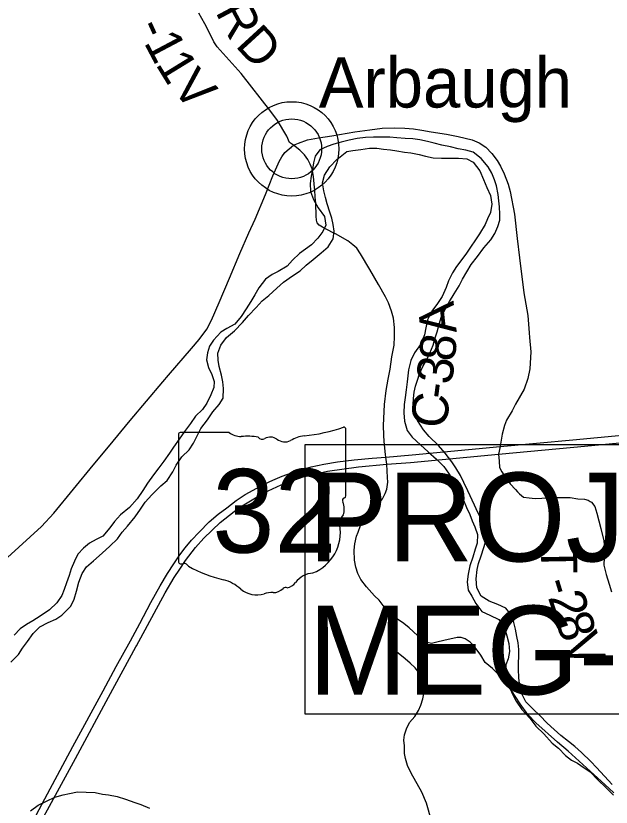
# Model space of a CAD drawing. Extents: x -13.7 to 34, y 0 to 32.3.
# Drawn here: x 23.927 to 24.865, y 17.887 to 19.134 of the extents above; entities that cross this region are included whole.
import ezdxf

# ---------------------------------------------------------------- set-up
doc = ezdxf.new("R2010")
doc.units = 0
for name, color, linetype in [('GM_X_County_Road', 7, 'Continuous'), ('GM_X_County_Road_Text', 7, 'Continuous'), ('GM_X_Major_River', 7, 'Continuous'), ('GM_X_Minor_River', 7, 'Continuous'), ('GM_X_State_Location', 7, 'Continuous'), ('GM_X_State_Route', 7, 'Continuous'), ('GM_X_State_Shield', 7, 'Continuous'), ('GM_X_Township_Road', 7, 'Continuous'), ('GM_X_Township_Road_Text', 7, 'Continuous'), ('GM_X_Unincorporated', 7, 'Continuous'), ('GM_X_Unincorporated_Location', 7, 'Continuous'), ('GM_X_Unincorporated_Text', 7, 'Continuous'), ('SH_Masking', 7, 'Continuous'), ('SH_Text', 7, 'Continuous')]:
    doc.layers.add(name, color=color, linetype=linetype)

msp = doc.modelspace()

# ---------------------------------------------------------------- linework, layer by layer
at = {"layer": 'GM_X_County_Road'}
for points in [[(23.8899, 18.259), (23.9313, 18.2966), (23.9669, 18.3292), (23.9865, 18.3504), (24.0483, 18.4258), (24.0727, 18.455), (24.1068, 18.4962), (24.1584, 18.5574), (24.1675, 18.568), (24.2035, 18.61), (24.2158, 18.6242), (24.2276, 18.6402), (24.235, 18.6547), (24.2473, 18.6825), (24.2635, 18.7206), (24.2801, 18.7596), (24.2943, 18.7922), (24.3038, 18.8138), (24.3201, 18.8525), (24.332, 18.882), (24.3401, 18.9009), (24.3421, 18.9046), (24.346, 18.9118), (24.3508, 18.9189), (24.3576, 18.9245), (24.3643, 18.9302), (24.3725, 18.9336), (24.3868, 18.939), (24.4038, 18.9419), (24.4249, 18.9452), (24.4614, 18.9515), (24.4849, 18.9545), (24.5045, 18.9572), (24.5239, 18.9579), (24.54, 18.9572), (24.554, 18.956), (24.5669, 18.9541), (24.5818, 18.9517), (24.6057, 18.9476), (24.6243, 18.9442), (24.6464, 18.939), (24.6575, 18.9343), (24.6679, 18.9274), (24.6771, 18.9173), (24.6857, 18.9065), (24.6909, 18.8971), (24.6968, 18.8855), (24.7031, 18.8691), (24.7064, 18.8574), (24.7132, 18.8215), (24.7174, 18.7834), (24.7211, 18.7529), (24.7279, 18.6974), (24.7338, 18.6617), (24.7363, 18.6345)], [(24.3979, 18.8598), (24.3976, 18.8639), (24.3961, 18.881), (24.3939, 18.893), (24.3909, 18.9007), (24.3872, 18.908), (24.3821, 18.915), (24.3744, 18.9227), (24.3643, 18.9302)], [(24.427, 18.7924), (24.4103, 18.8011), (24.4051, 18.8041), (24.4018, 18.8079), (24.4006, 18.8122), (24.4005, 18.8186), (24.3999, 18.8388), (24.3987, 18.8485), (24.3979, 18.8598)], [(24.5117, 18.4275), (24.5101, 18.4386), (24.5096, 18.4425), (24.5077, 18.4633), (24.5071, 18.4731), (24.5062, 18.4882), (24.508, 18.5217), (24.5108, 18.5437), (24.5138, 18.5615), (24.5167, 18.5772), (24.5194, 18.5966), (24.5231, 18.615), (24.5239, 18.6289), (24.5237, 18.6431), (24.522, 18.6576), (24.5193, 18.6688), (24.5142, 18.6819), (24.5096, 18.6911), (24.4987, 18.7109), (24.4847, 18.7344), (24.4701, 18.7593), (24.4645, 18.7681), (24.4581, 18.7735), (24.4502, 18.7798), (24.4305, 18.7906), (24.427, 18.7924)], [(24.7363, 18.6345), (24.7369, 18.6274), (24.7387, 18.6045), (24.7372, 18.5776), (24.7339, 18.5624), (24.7285, 18.5455), (24.7146, 18.5219), (24.7091, 18.5116), (24.7005, 18.4966), (24.6971, 18.4883), (24.6935, 18.4749), (24.6911, 18.4592), (24.6903, 18.4555), (24.6879, 18.4434)], [(24.4794, 18.234), (24.4709, 18.2456), (24.4661, 18.2551), (24.4627, 18.2652), (24.4606, 18.2759), (24.4602, 18.2919), (24.461, 18.3018), (24.4636, 18.3141), (24.4665, 18.3204), (24.4701, 18.3305), (24.4779, 18.3412), (24.4863, 18.3503), (24.4958, 18.3619), (24.5046, 18.3728), (24.5091, 18.3812), (24.5118, 18.3882), (24.5131, 18.3989), (24.5126, 18.4063), (24.5117, 18.4275)], [(24.5166, 18.1887), (24.5137, 18.1928), (24.511, 18.1974), (24.5074, 18.2024), (24.4996, 18.213), (24.492, 18.2199), (24.4794, 18.234)], [(24.5823, 17.8652), (24.5742, 17.8927), (24.5669, 17.9101), (24.5498, 17.9401), (24.5445, 17.9522), (24.541, 17.9633), (24.5396, 17.9709), (24.5394, 17.9833), (24.5387, 17.9921), (24.5397, 18.0004), (24.5428, 18.0101), (24.5475, 18.02), (24.5556, 18.0295), (24.5616, 18.0389), (24.5655, 18.0473), (24.5686, 18.0574), (24.5703, 18.0678), (24.5701, 18.0751), (24.5687, 18.0839), (24.5672, 18.089), (24.5625, 18.0981), (24.5564, 18.1062), (24.5486, 18.1134), (24.5404, 18.1207), (24.5321, 18.1274), (24.5248, 18.133), (24.5185, 18.1388), (24.5164, 18.1417), (24.5153, 18.1463), (24.5144, 18.1512), (24.5143, 18.1573), (24.5149, 18.1645), (24.515, 18.1698), (24.516, 18.1767), (24.5166, 18.1887)]]:
    msp.add_lwpolyline(points, dxfattribs=at)
at = {"layer": 'GM_X_Major_River'}
for points in [[(24.6866, 18.802), (24.6897, 18.8123), (24.6897, 18.8217), (24.6893, 18.8331), (24.6885, 18.8426), (24.6874, 18.8529), (24.6848, 18.8665), (24.6817, 18.876), (24.6772, 18.8863), (24.6715, 18.8965), (24.6605, 18.9094), (24.6476, 18.9193), (24.6362, 18.9223), (24.6241, 18.9246), (24.6119, 18.9277), (24.5986, 18.9307), (24.5861, 18.9338), (24.5759, 18.936), (24.5637, 18.9387), (24.5527, 18.9402), (24.5406, 18.941), (24.5273, 18.9422), (24.5163, 18.9429), (24.4908, 18.9429), (24.4783, 18.9426), (24.465, 18.9407), (24.4525, 18.9384), (24.4399, 18.9354), (24.4281, 18.932), (24.4175, 18.9286), (24.4061, 18.9233), (24.3985, 18.913), (24.3962, 18.9024), (24.3947, 18.8925), (24.3924, 18.8815), (24.3909, 18.8698), (24.3912, 18.8576), (24.3958, 18.8447), (24.4034, 18.8318), (24.4132, 18.8182), (24.4155, 18.8045), (24.4109, 18.7943), (24.4029, 18.784), (24.3931, 18.7734), (24.3836, 18.7662), (24.3741, 18.7598), (24.363, 18.7491), (24.3547, 18.7397), (24.3402, 18.7313), (24.3307, 18.7264), (24.3205, 18.7192), (24.3098, 18.7055), (24.3034, 18.6942), (24.2973, 18.6839), (24.29, 18.6722), (24.2821, 18.6604), (24.2718, 18.6483), (24.2593, 18.6411), (24.2498, 18.6354), (24.2384, 18.6229), (24.2319, 18.6134), (24.2288, 18.6031), (24.2273, 18.5918), (24.2303, 18.5796), (24.2356, 18.5686), (24.2394, 18.558), (24.239, 18.5485), (24.2341, 18.5367), (24.2276, 18.5238), (24.2208, 18.5136), (24.2101, 18.503), (24.2018, 18.4916), (24.1926, 18.4787), (24.1843, 18.4666), (24.1755, 18.4541), (24.1691, 18.4446), (24.1599, 18.4321), (24.1523, 18.4214), (24.1436, 18.4108), (24.1341, 18.3972), (24.1268, 18.3858), (24.1181, 18.3725), (24.1059, 18.3592), (24.0919, 18.3475), (24.082, 18.3372), (24.0751, 18.327), (24.0637, 18.3141), (24.0531, 18.3088), (24.0428, 18.3027), (24.0333, 18.2952), (24.0246, 18.2857), (24.0193, 18.2747), (24.0139, 18.2625), (24.0109, 18.2519), (24.0067, 18.2402), (24.0029, 18.2299), (23.9991, 18.2204), (23.9915, 18.2087), (23.9797, 18.1977), (23.9649, 18.1878), (23.9535, 18.1806)], [(23.9185, 18.115), (23.931, 18.1275), (23.9371, 18.137), (23.9451, 18.148), (23.9538, 18.1605), (23.9645, 18.1707), (23.9778, 18.1776), (23.9899, 18.1829), (23.9994, 18.1893), (24.0131, 18.2033), (24.0185, 18.2143), (24.0223, 18.2272), (24.0261, 18.2413), (24.0314, 18.2549), (24.0383, 18.2656), (24.0493, 18.275), (24.063, 18.2872), (24.0747, 18.2982), (24.0869, 18.3099), (24.0945, 18.3202), (24.1029, 18.3296), (24.115, 18.3444), (24.123, 18.3562), (24.1306, 18.3676), (24.1409, 18.3789), (24.1553, 18.3934), (24.1652, 18.4017), (24.174, 18.4153), (24.1793, 18.4256), (24.1884, 18.4389), (24.2002, 18.4502), (24.207, 18.4605), (24.2124, 18.4722), (24.2185, 18.4836), (24.2287, 18.4973), (24.2375, 18.5098), (24.2474, 18.5215), (24.2534, 18.5314), (24.2542, 18.5466), (24.2531, 18.5572), (24.2508, 18.5675), (24.2474, 18.5815), (24.2455, 18.5914), (24.2452, 18.6024), (24.2497, 18.6149), (24.2589, 18.627), (24.2714, 18.6376), (24.2843, 18.6509), (24.2935, 18.6619), (24.3056, 18.6744), (24.3151, 18.685), (24.3254, 18.6934), (24.3383, 18.7051), (24.3489, 18.7142), (24.363, 18.7245), (24.3748, 18.7324), (24.3847, 18.7412), (24.3957, 18.7499), (24.4082, 18.7605), (24.4192, 18.77), (24.4272, 18.7825), (24.4284, 18.795), (24.4269, 18.8056), (24.425, 18.8151), (24.422, 18.8246), (24.4174, 18.8379), (24.4148, 18.8478), (24.4121, 18.8584), (24.4102, 18.8709), (24.4133, 18.8834), (24.422, 18.8963), (24.4327, 18.9081), (24.4486, 18.9202), (24.4581, 18.9221), (24.4707, 18.9236), (24.4843, 18.9255), (24.4961, 18.9259), (24.5064, 18.9243), (24.5174, 18.9232), (24.5272, 18.9217), (24.5394, 18.9194), (24.5493, 18.9182), (24.5629, 18.9159), (24.5728, 18.9133), (24.585, 18.9106), (24.5979, 18.9098), (24.6248, 18.9098), (24.6381, 18.9087), (24.6476, 18.9037), (24.6582, 18.8901), (24.6643, 18.8764), (24.6696, 18.8635), (24.6753, 18.851), (24.6775, 18.8373), (24.6752, 18.8244), (24.6707, 18.8145), (24.6665, 18.8051), (24.6577, 18.7907)], [(24.8668, 17.9222), (24.8551, 17.9355), (24.8426, 17.9492), (24.8335, 17.9587), (24.8187, 17.9727), (24.808, 17.9822), (24.7982, 17.9902), (24.786, 17.9993), (24.7754, 18.0092), (24.7644, 18.0191), (24.753, 18.0309), (24.7432, 18.0404), (24.731, 18.0525), (24.7242, 18.0662), (24.7212, 18.0779), (24.72, 18.0897), (24.7193, 18.1045), (24.7193, 18.114), (24.7197, 18.1242), (24.7197, 18.1352), (24.7186, 18.1455), (24.7167, 18.1557), (24.7144, 18.1671), (24.7122, 18.1778), (24.7076, 18.1899), (24.6993, 18.2002), (24.6868, 18.2062), (24.6731, 18.2112), (24.6602, 18.2195), (24.6537, 18.2324), (24.6526, 18.2465), (24.6542, 18.2613), (24.6564, 18.2708), (24.6606, 18.2829), (24.6648, 18.2962), (24.6686, 18.308), (24.6683, 18.3178), (24.6652, 18.3281), (24.6618, 18.3383), (24.655, 18.3512), (24.6501, 18.3626), (24.6395, 18.3854), (24.633, 18.3987), (24.6281, 18.4097), (24.6205, 18.4215), (24.6141, 18.4313), (24.6038, 18.445), (24.5932, 18.4568), (24.5784, 18.4712), (24.5697, 18.4818), (24.5602, 18.4963), (24.5538, 18.5095), (24.5534, 18.5209), (24.5538, 18.5308), (24.555, 18.541), (24.5569, 18.5505), (24.5599, 18.56), (24.563, 18.5699), (24.5687, 18.5816), (24.574, 18.5915), (24.5797, 18.6025), (24.585, 18.615), (24.5877, 18.6264), (24.5911, 18.6359), (24.5942, 18.648), (24.598, 18.6605), (24.6045, 18.6734), (24.6105, 18.6837), (24.6181, 18.6958), (24.6258, 18.7087), (24.6311, 18.7193), (24.6448, 18.7421), (24.6547, 18.755), (24.6649, 18.7683), (24.6756, 18.7812), (24.682, 18.7914), (24.6866, 18.802)], [(24.6577, 18.7907), (24.6516, 18.7812), (24.6437, 18.7698), (24.6372, 18.7599), (24.63, 18.7501), (24.6216, 18.7391), (24.6155, 18.7292), (24.6091, 18.7163), (24.6052, 18.7061), (24.5988, 18.692), (24.5915, 18.6807), (24.5824, 18.6689), (24.576, 18.6552), (24.5733, 18.6423), (24.571, 18.6313), (24.5649, 18.6162), (24.5554, 18.6029), (24.5493, 18.5908), (24.5459, 18.5763), (24.5447, 18.5669), (24.544, 18.5574), (24.5424, 18.5445), (24.5405, 18.5327), (24.539, 18.5213), (24.5386, 18.5084), (24.5397, 18.4951), (24.5435, 18.4803), (24.5515, 18.4701), (24.5647, 18.4579), (24.5769, 18.4469), (24.5902, 18.4351), (24.6015, 18.4237), (24.6087, 18.4131), (24.6152, 18.4032), (24.6212, 18.3922), (24.6269, 18.382), (24.6326, 18.3706), (24.6375, 18.3592), (24.6425, 18.3482), (24.6463, 18.3383), (24.6504, 18.3285), (24.6546, 18.3167), (24.6542, 18.3027), (24.6511, 18.2932), (24.6473, 18.281), (24.6424, 18.267), (24.6397, 18.2541), (24.6382, 18.2416), (24.6401, 18.2287), (24.6458, 18.2192), (24.6522, 18.2078), (24.6613, 18.1952), (24.6742, 18.1892), (24.6882, 18.1823), (24.6973, 18.1698), (24.7011, 18.1569), (24.7042, 18.1447), (24.7053, 18.1322), (24.703, 18.1205), (24.6992, 18.111), (24.6996, 18.0988), (24.7014, 18.089), (24.7041, 18.0795), (24.7086, 18.0669), (24.7158, 18.0537), (24.7246, 18.0407), (24.7371, 18.0271), (24.7466, 18.0145), (24.7595, 18.002), (24.7723, 17.9872), (24.7826, 17.9796), (24.7932, 17.9678), (24.8027, 17.9606), (24.8126, 17.9557), (24.8228, 17.9488), (24.8323, 17.942), (24.8444, 17.9295), (24.857, 17.9173), (24.8691, 17.9055)], [(23.9535, 18.1806), (23.9436, 18.1745), (23.9333, 18.1677), (23.9238, 18.1575)]]:
    msp.add_lwpolyline(points, dxfattribs=at)
at = {"layer": 'GM_X_Minor_River'}
msp.add_lwpolyline([(23.9495, 17.8805), (23.962, 17.8896), (23.9752, 17.8961), (23.9881, 17.9022), (24.0014, 17.906), (24.0112, 17.9083), (24.0241, 17.9106), (24.0377, 17.9102), (24.0517, 17.9095), (24.0631, 17.9068), (24.0726, 17.9061), (24.0862, 17.9034), (24.0995, 17.8993), (24.1143, 17.894), (24.1237, 17.8906), (24.1374, 17.8849)], dxfattribs=at)
at = {"layer": 'GM_X_State_Route'}
for points in [[(23.9411, 17.8413), (23.9763, 17.9076), (24.0167, 17.9821), (24.0643, 18.0698), (24.085, 18.1084), (24.1074, 18.1487), (24.1219, 18.1759), (24.1396, 18.2091), (24.1544, 18.2358), (24.1659, 18.255), (24.176, 18.2703), (24.185, 18.2843), (24.1937, 18.2953), (24.2039, 18.3075), (24.2158, 18.3201), (24.2313, 18.3363), (24.2456, 18.3484), (24.2592, 18.3588), (24.274, 18.37), (24.2882, 18.3797), (24.3066, 18.3894), (24.3194, 18.3965), (24.3321, 18.4022), (24.3467, 18.4086), (24.3615, 18.4139), (24.3758, 18.4187), (24.3926, 18.4233), (24.4122, 18.4274), (24.4337, 18.4312), (24.4602, 18.4341), (24.4887, 18.4369), (24.5101, 18.4386), (24.5514, 18.4423), (24.6903, 18.4555), (24.8051, 18.4658), (24.9497, 18.4797)], [(23.9463, 17.8264), (23.9828, 17.8937), (24.0207, 17.9635), (24.073, 18.0602), (24.116, 18.1396), (24.1167, 18.141), (24.1622, 18.2243), (24.1761, 18.2485), (24.185, 18.262), (24.1941, 18.2755), (24.2099, 18.2958), (24.2229, 18.3106), (24.2487, 18.3353), (24.2783, 18.3584), (24.3179, 18.3824), (24.345, 18.395), (24.3797, 18.4073), (24.418, 18.4166), (24.4671, 18.4233), (24.5117, 18.4275), (24.549, 18.4302), (24.6879, 18.4434), (24.8067, 18.4541), (24.9512, 18.4679)]]:
    msp.add_lwpolyline(points, dxfattribs=at)
at = {"layer": 'GM_X_State_Shield'}
for p, q in [((24.4469, 18.3776), (24.4469, 18.4823)), ((24.1832, 18.4739), (24.1832, 18.2738)), ((24.2631, 18.4774), (24.1858, 18.4774)), ((24.4469, 18.3777), (24.4469, 18.3776))]:
    msp.add_line(p, q, dxfattribs=at)
for centre, radius, start, end in [((24.353, 18.7502), 0.2796, 275.8445, 288.9065), ((24.444, 18.4828), 0.00294, 351.8621, 97.738), ((24.1863, 18.4744), 0.00305, 98.1301, 188.1301), ((24.2814, 18.5006), 0.0296, 231.6195, 271.1119), ((24.2913, 18.365), 0.1064, 80.4867, 94.9883), ((24.3154, 18.4754), 0.00855, 219.7921, 297.1024), ((24.328, 18.4523), 0.0178, 54.4667, 119.1411), ((24.3886, 18.4162), 0.0563, 97.3462, 120.7689), ((24.3509, 18.484), 0.0214, 233.8562, 294.8282), ((24.4462, 18.37), 0.00454, 107.944, 210.337), ((24.4438, 18.3772), 0.00314, 289.6038, 7.7341), ((24.4173, 18.3567), 0.0273, 340.033, 23.6496), ((24.4574, 18.3338), 0.0198, 136.8065, 186.9296), ((24.3686, 18.3205), 0.0699, 292.3089, 8.9858), ((24.1863, 18.2734), 0.00308, 171.9584, 258.3066), ((24.1868, 18.2938), 0.0235, 267.339, 280.6039), ((24.1916, 18.2623), 0.00848, 29.7484, 93.2717), ((24.2986, 18.4421), 0.2019, 240.4129, 257.1985), ((24.2384, 18.1839), 0.0632, 47.1842, 75.836), ((24.3981, 18.2176), 0.0383, 94.4031, 142.5768), ((24.3522, 18.2269), 0.00601, 65.7517, 132.6484), ((24.3496, 18.2544), 0.0226, 282.8732, 323.2771), ((24.3068, 18.2613), 0.0401, 230.7004, 286.2918), ((24.3299, 18.1921), 0.0329, 85.6951, 111.2099), ((24.3328, 18.2463), 0.0214, 268.777, 315.5493)]:
    msp.add_arc(centre, radius, start, end, dxfattribs=at)
at = {"layer": 'GM_X_Township_Road'}
for points in [[(24.3643, 18.9302), (24.3583, 18.9347), (24.3538, 18.9446), (24.3395, 18.9691), (24.3289, 18.9837), (24.2819, 19.0434), (24.2443, 19.0856), (24.2388, 19.0936), (24.2319, 19.1078), (24.2249, 19.1219), (24.2151, 19.1386)], [(24.6879, 18.4434), (24.6886, 18.4319), (24.6892, 18.4219), (24.693, 18.4151), (24.7064, 18.3965), (24.7146, 18.3873), (24.7178, 18.3839)], [(24.7178, 18.3839), (24.721, 18.3805), (24.7272, 18.3755), (24.7364, 18.3741), (24.7454, 18.3731), (24.7562, 18.3737), (24.778, 18.3751), (24.7914, 18.3751), (24.801, 18.3747), (24.8128, 18.3729), (24.8236, 18.3721), (24.829, 18.3707), (24.8326, 18.3686)], [(24.8326, 18.3686), (24.8344, 18.3675), (24.8396, 18.3609), (24.843, 18.3501), (24.8492, 18.3259), (24.8538, 18.3065), (24.8552, 18.2953), (24.8544, 18.2801), (24.8538, 18.2681), (24.8576, 18.2535), (24.8622, 18.2383), (24.8658, 18.2261)], [(24.8695, 17.9093), (24.8556, 17.9223), (24.7979, 17.9746), (24.7809, 17.9892), (24.7466, 18.0196), (24.7343, 18.0325), (24.7217, 18.0496), (24.7084, 18.0705), (24.6935, 18.0894), (24.6781, 18.105), (24.6668, 18.1149), (24.6598, 18.126), (24.6494, 18.1402), (24.6433, 18.1466), (24.6354, 18.152), (24.629, 18.1539), (24.6227, 18.1541), (24.6018, 18.1495), (24.5905, 18.1466), (24.5823, 18.1446), (24.5753, 18.1463), (24.5698, 18.1488), (24.5648, 18.1518), (24.56, 18.1573), (24.5468, 18.1693), (24.5387, 18.1761), (24.5269, 18.1843), (24.5166, 18.1887)]]:
    msp.add_lwpolyline(points, dxfattribs=at)
at = {"layer": 'GM_X_Unincorporated'}
for radius in [0.0744, 0.0472]:
    msp.add_circle((24.3617, 18.9246), radius, dxfattribs=at)
at = {"layer": 'GM_X_Unincorporated_Location'}
msp.add_line((24.3617, 18.9246), (24.3617, 18.9246), dxfattribs=at)
at = {"layer": 'SH_Masking'}
msp.add_lwpolyline([(24.3829, 18.4583), (26.173, 18.4583), (26.173, 18.0332), (24.3829, 18.0332)], close=True, dxfattribs=at)
at = {"layer": 'SH_Text'}
msp.add_lwpolyline([(24.3829, 18.4583), (26.173, 18.4583), (26.173, 18.0332), (24.3829, 18.0332)], close=True, dxfattribs=at)

# ---------------------------------------------------------------- texts
at = {"layer": 'GM_X_County_Road_Text'}
for s, rotation, p in [('A', 95.9709, (24.622, 18.6354)), ('8', 84.4097, (24.6186, 18.5881)), ('3', 82.6442, (24.6139, 18.5515)), ('-', 82.5248, (24.6109, 18.5282)), ('C', 82.4848, (24.6048, 18.4819))]:
    msp.add_text(s, height=0.0568, rotation=rotation, dxfattribs=at).set_placement(p)
at = {"layer": 'GM_X_State_Location'}
for s in ['s', 'r']:
    msp.add_text(s, height=0.000189, dxfattribs=at).set_placement((24.3121, 18.3606))
msp.add_text('32', height=0.000189, rotation=0, dxfattribs=at).set_placement((24.2644, 18.3468))
at = {"layer": 'GM_X_State_Shield'}
msp.add_text('32', height=0.13184, dxfattribs=at).set_placement((24.2364, 18.2879))
at = {"layer": 'GM_X_Township_Road_Text'}
for s, rotation, p in [('R', 298.0629, (24.2405, 19.1408)), ('-', 294.4269, (24.1165, 19.1172)), ('D', 312.5156, (24.2714, 19.0871)), ('1', 297.8754, (24.1278, 19.0926)), ('1', 301.5417, (24.1461, 19.0582)), ('V', 311.4533, (24.1708, 19.0198)), ('T', 271.0886, (24.7546, 18.3004)), ('-', 287.1894, (24.7582, 18.2408)), ('2', 287.9924, (24.7654, 18.2177)), ('8', 289.0056, (24.7765, 18.1834)), ('V', 289.8755, (24.7882, 18.1494))]:
    msp.add_text(s, height=0.0568, rotation=rotation, dxfattribs=at).set_placement(p)
at = {"layer": 'GM_X_Unincorporated_Text'}
msp.add_text('Arbaugh', height=0.07898, rotation=0, dxfattribs=at).set_placement((24.4044, 18.9898))
at = {"layer": 'SH_Text'}
for s, p in [('PROJECT LOCATION', (24.388, 18.2741)), ('MEG-689-01.87', (24.388, 18.0641))]:
    msp.add_text(s, height=0.14, dxfattribs=at).set_placement(p)

doc.saveas('drawing.dxf')
